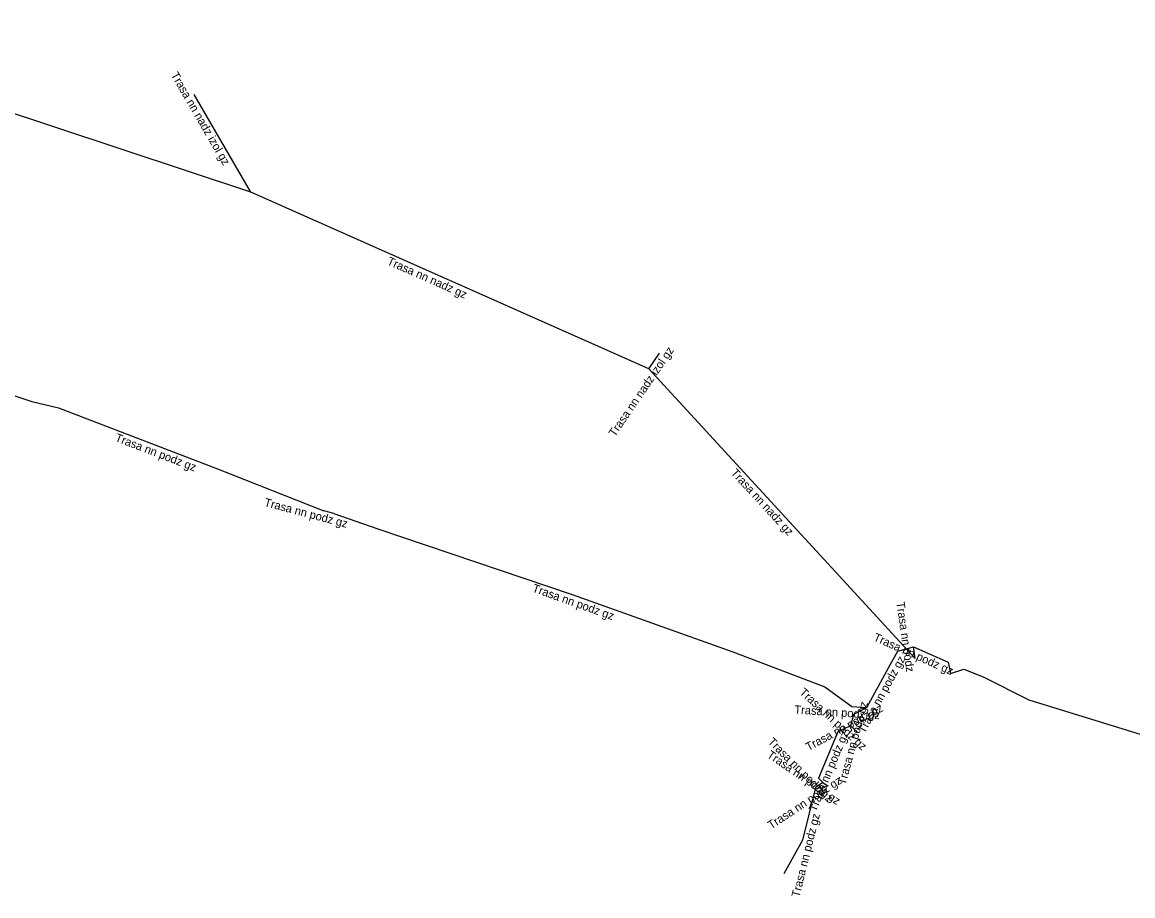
# Model space of a CAD drawing. Extents: x -743572 to -742920, y -1027115 to -1026442.
# Drawn here: x -743055.3 to -742988.4, y -1026760.9 to -1026708.3 of the extents above; entities that cross this region are included whole.
import ezdxf

# ---------------------------------------------------------------- set-up
doc = ezdxf.new("R2010")
doc.units = 0
doc.layers.add('Popiskový text - Ostatní atributy Trasy', color=7, linetype='Continuous')
doc.layers.add('Spojnice NN', color=7, linetype='Continuous')

msp = doc.modelspace()

# ---------------------------------------------------------------- linework, layer by layer
at = {"layer": 'Spojnice NN'}
for points in [[(-743041.513, -1026718.545), (-743072.421, -1026708.301)], [(-743041.513, -1026718.545), (-743044.927, -1026712.648)], [(-743017.548, -1026729.18), (-743041.513, -1026718.545)], [(-743064.362, -1026728.085), (-743062.451, -1026728.615), (-743054.707, -1026731.157)], [(-743017.548, -1026729.18), (-743016.907, -1026728.239)], [(-743001.488, -1026746.642), (-743017.548, -1026729.18)], [(-743054.707, -1026731.157), (-743053.113, -1026731.536), (-743043.523, -1026735.221), (-743037.125, -1026737.739)], [(-743036.51, -1026737.902), (-743037.125, -1026737.739)], [(-743036.51, -1026737.902), (-743033.867, -1026738.823), (-743022.153, -1026742.788), (-743012.481, -1026746.245), (-743006.946, -1026748.362), (-743005.303, -1026749.542)], [(-743004.411, -1026749.602), (-743002.988, -1026746.987), (-743002.529, -1026746.21), (-743001.59, -1026745.932)], [(-743001.59, -1026745.932), (-742999.501, -1026746.866), (-742999.361, -1026747.543)], [(-743001.488, -1026746.642), (-743001.59, -1026745.932)], [(-742999.361, -1026747.543), (-742998.56, -1026747.297), (-742997.401, -1026747.756), (-742994.654, -1026749.141), (-742986.059, -1026751.781), (-742984.645, -1026751.899), (-742982.792, -1026751.491), (-742979.651, -1026750.123), (-742979.096, -1026750.071), (-742974.97, -1026751.364), (-742967.14, -1026753.692)], [(-743005.303, -1026749.542), (-743004.411, -1026749.602)], [(-743004.411, -1026749.602), (-743005.201, -1026750.027)], [(-743005.201, -1026750.027), (-743005.386, -1026750.705)], [(-743005.386, -1026750.705), (-743006.156, -1026751.061), (-743007.32, -1026753.858)], [(-743005.386, -1026750.705), (-743004.994, -1026751.062)], [(-743007.32, -1026753.858), (-743007.052, -1026754.124)], [(-743007.493, -1026754.414), (-743008.279, -1026757.587), (-743009.404, -1026759.623)], [(-743007.052, -1026754.124), (-743007.493, -1026754.414)], [(-743007.052, -1026754.124), (-743006.729, -1026754.347)]]:
    msp.add_lwpolyline(points, dxfattribs=at)

# ---------------------------------------------------------------- texts
at = {"layer": 'Popiskový text - Ostatní atributy Trasy'}
for s, rotation, p in [('Trasa nn nadz izol gz', 300.0682, (-743046.356, -1026711.478)), ('Trasa nn nadz gz', 336.06968, (-743033.353, -1026722.877)), ('Trasa nn nadz izol gz', 55.73769, (-743019.582, -1026733.32)), ('Trasa nn podz gz', 338.98051, (-743049.741, -1026733.528)), ('Trasa nn nadz gz', 312.6051, (-743012.632, -1026735.485)), ('Trasa nn podz gz', 345.1556, (-743040.748, -1026737.451)), ('Trasa nn podz gz', 340.33192, (-743024.601, -1026742.604)), ('Trasa nn podz', 278.17529, (-743002.63, -1026743.264)), ('Trasa nn podz gz', 335.9104, (-743004.05, -1026745.544)), ('Trasa nn podz gz', 61.44637, (-743004.54, -1026751.199)), ('Trasa nn podz gz', 317.67543, (-743008.506, -1026748.742)), ('Trasa nn podz gz', 74.73773, (-743005.692, -1026754.293)), ('Trasa nn podz gz', 356.15182, (-743008.786, -1026749.959)), ('Trasa nn podz gz', 28.27913, (-743007.927, -1026752.232)), ('Trasa nn podz gz', 67.40487, (-743007.471, -1026755.913)), ('Trasa nn podz gz', 315.21459, (-743010.408, -1026751.71)), ('Trasa nn podz gz', 325.37871, (-743010.464, -1026752.559)), ('Trasa nn podz gz', 33.32877, (-743010.169, -1026756.951)), ('Trasa nn podz gz', 76.08704, (-743008.471, -1026761.066))]:
    msp.add_text(s, height=0.5, rotation=rotation, dxfattribs=at).set_placement(p)

doc.saveas('drawing.dxf')
